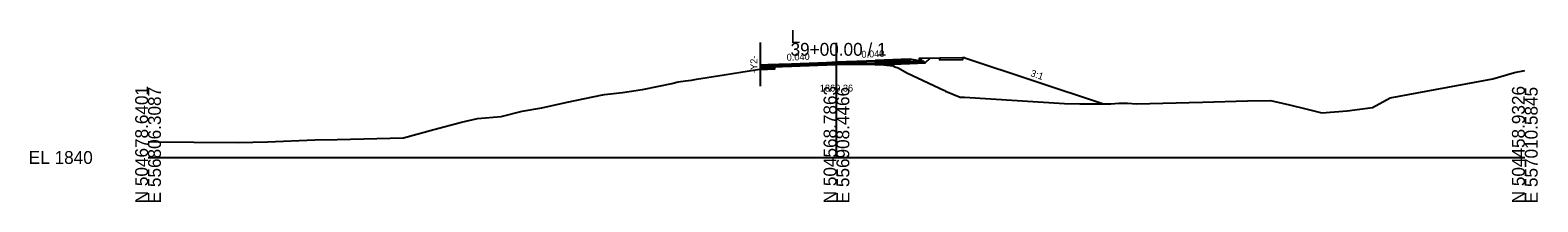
# Model space of a CAD drawing. Extents: x -26 to 4603, y -10 to 4703.
# Drawn here: x 974.3 to 1302.8, y 4395.3 to 4432.8 of the extents above; entities that cross this region are included whole.
import ezdxf

# ---------------------------------------------------------------- set-up
doc = ezdxf.new("R2010")
doc.units = 0
for name, color, linetype in [('Default', 7, 'Continuous'), ('Exist Cross Section Cell', 7, 'Continuous'), ('Exist XS Ground Line', 7, 'Continuous'), ('Prop CMT Pvmt Course 1', 7, 'Continuous'), ('Prop CMT Pvmt Course 2', 7, 'Continuous'), ('Prop CMT Pvmt Course 3', 7, 'Continuous'), ('Prop CMT Pvmt Milling', 7, 'Continuous'), ('Prop CMT Shear Line', 7, 'Continuous'), ('Prop CMT Shld Paved Course 2', 7, 'Continuous'), ('Prop CMT Subgrade Earthwork', 7, 'Continuous'), ('Prop Conc 4in Sidewalk', 7, 'Continuous'), ('Prop Conc Curb and Gutter', 7, 'Continuous'), ('Prop Corridor Mesh Bottom', 7, 'Continuous'), ('Prop XS Finish Grade', 7, 'Continuous'), ('Prop XS Label Text', 7, 'Continuous'), ('Prop XS Shear Point Element', 7, 'Continuous'), ('Prop XS Shear Point Label', 7, 'Continuous'), ('Prop XS SS Elevation Text', 7, 'Continuous')]:
    doc.layers.add(name, color=color, linetype=linetype)

msp = doc.modelspace()

# ---------------------------------------------------------------- linework, layer by layer
at = {"layer": 'Exist Cross Section Cell'}
for p, q in [((1150, 4405), (1150, 4430)), ((1000, 4405), (1150, 4405)), ((1150, 4405), (1300, 4405))]:
    msp.add_line(p, q, dxfattribs=at)
at = {"layer": 'Exist XS Ground Line'}
msp.add_lwpolyline([(1000, 4408.46), (1002.27, 4408.4), (1009.98, 4408.34), (1019.64, 4408.25), (1026.01, 4408.45), (1036.39, 4408.84), (1041.2, 4408.91), (1055.66, 4409.27), (1062.27, 4411.12), (1068.29, 4412.73), (1071.75, 4413.5), (1076.96, 4413.98), (1081.53, 4415.08), (1085.8, 4415.85), (1091.34, 4417.05), (1099.05, 4418.67), (1099.12, 4418.68), (1099.43, 4418.72), (1103.35, 4419.21), (1106.31, 4419.61), (1107.18, 4419.73), (1107.77, 4419.84), (1111.33, 4420.57), (1114.11, 4421.18), (1115.53, 4421.53), (1117.09, 4421.73), (1118.41, 4421.91), (1119.52, 4422.09), (1125.54, 4423.04), (1130.98, 4423.92), (1136.01, 4424.74), (1136.36, 4424.8), (1136.6, 4424.82), (1137.42, 4424.9), (1138.22, 4424.94), (1147.88, 4425.35), (1156.59, 4425.39), (1158.5, 4425.39), (1159.18, 4425.32), (1160.32, 4425.21), (1162.39, 4424.97), (1162.75, 4424.75), (1163.43, 4424.54), (1165.36, 4423.47), (1173.52, 4419.63), (1173.75, 4419.45), (1176.93, 4418.2), (1177.14, 4418.14), (1177.89, 4418.13), (1199.71, 4416.79), (1203.04, 4416.68), (1209.81, 4416.7), (1211.56, 4416.88), (1213.4, 4416.86), (1215.35, 4416.7), (1229.8, 4417.08), (1239.59, 4417.38), (1244.6, 4417.46), (1248.75, 4416.5), (1252.55, 4415.54), (1255.77, 4414.73), (1261.32, 4415.19), (1266.84, 4415.94), (1270.64, 4418), (1293.02, 4422.14), (1297.76, 4423.56), (1300, 4423.98)], dxfattribs=at)
at = {"layer": 'Prop CMT Pvmt Course 1'}
for points in [[(1150, 4425.84), (1150, 4425.84), (1150, 4425.36), (1150, 4425.36), (1150, 4425.36), (1147.88, 4425.35), (1147.88, 4425.35), (1138.22, 4424.94), (1138.22, 4424.94), (1137.42, 4424.9), (1136.6, 4424.82), (1136.6, 4424.82), (1136.6, 4424.82), (1136.6, 4425.3), (1136.6, 4425.3), (1137.42, 4425.33), (1138.22, 4425.37), (1138.22, 4425.37), (1147.88, 4425.75), (1147.88, 4425.75), (1150, 4425.84)], [(1158.5, 4426.18), (1158.5, 4425.39), (1158.5, 4425.39), (1156.59, 4425.39), (1156.59, 4425.39), (1150, 4425.36), (1150, 4425.36), (1150, 4425.36), (1150, 4425.84), (1150, 4425.84), (1156.59, 4426.1), (1156.59, 4426.1), (1158.5, 4426.18)], [(1166, 4426.48), (1158.5, 4426.18), (1158.5, 4425.93), (1158.5, 4425.93), (1166, 4426.23), (1166, 4426.23), (1166, 4426.23), (1166, 4426.48), (1166, 4426.48)], [(1136.6, 4425.3), (1133.43, 4425.17), (1133.43, 4424.92), (1133.43, 4424.92), (1136.6, 4425.05), (1136.6, 4425.05), (1136.6, 4425.05), (1136.6, 4425.3), (1136.6, 4425.3)]]:
    msp.add_lwpolyline(points, dxfattribs=at)
at = {"layer": 'Prop CMT Pvmt Course 2'}
for points in [[(1166, 4426.23), (1158.5, 4425.93), (1158.5, 4425.59), (1158.5, 4425.59), (1166, 4425.89), (1166, 4425.89), (1166, 4425.89), (1166, 4426.23), (1166, 4426.23)], [(1136.6, 4425.05), (1133.43, 4424.92), (1133.43, 4424.59), (1133.43, 4424.59), (1136.6, 4424.72), (1136.6, 4424.72), (1136.6, 4424.72), (1136.6, 4425.05), (1136.6, 4425.05)]]:
    msp.add_lwpolyline(points, dxfattribs=at)
at = {"layer": 'Prop CMT Pvmt Course 3'}
for points in [[(1166, 4425.89), (1158.5, 4425.59), (1158.5, 4425.22), (1158.5, 4425.22), (1166, 4425.52), (1166, 4425.52), (1166, 4425.52), (1166, 4425.89), (1166, 4425.89)], [(1166, 4425.89), (1166, 4425.89), (1166, 4425.52), (1166, 4425.52), (1166, 4425.52), (1169.36, 4425.65), (1169.36, 4425.65), (1169, 4426.01), (1166, 4425.89)], [(1136.6, 4424.72), (1133.43, 4424.59), (1133.43, 4424.22), (1133.43, 4424.22), (1136.6, 4424.34), (1136.6, 4424.34), (1136.6, 4424.34), (1136.6, 4424.72), (1136.6, 4424.72)]]:
    msp.add_lwpolyline(points, dxfattribs=at)
at = {"layer": 'Prop CMT Pvmt Milling'}
for points in [[(1136.6, 4424.82), (1136.6, 4424.82), (1137.42, 4424.9), (1138.22, 4424.94), (1138.22, 4424.94), (1147.88, 4425.35), (1147.88, 4425.35), (1150, 4425.36), (1150, 4425.36)], [(1158.5, 4425.39), (1156.59, 4425.39), (1156.59, 4425.39), (1150, 4425.36), (1150, 4425.36)]]:
    msp.add_lwpolyline(points, dxfattribs=at)
at = {"layer": 'Prop CMT Shld Paved Course 2'}
for points in [[(1150, 4425.59), (1150, 4425.59), (1150, 4425.25), (1150, 4425.25), (1150, 4425.25), (1147.88, 4425.17), (1147.88, 4425.17), (1138.22, 4424.78), (1138.22, 4424.78), (1137.42, 4424.75), (1136.6, 4424.72), (1136.6, 4424.72), (1136.6, 4424.72), (1136.6, 4425.05), (1136.6, 4425.05), (1137.42, 4425.08), (1138.22, 4425.12), (1138.22, 4425.12), (1147.88, 4425.5), (1147.88, 4425.5), (1150, 4425.59)], [(1158.5, 4425.93), (1158.5, 4425.39), (1158.5, 4425.39), (1156.59, 4425.39), (1156.59, 4425.39), (1152.96, 4425.37), (1152.96, 4425.37), (1150, 4425.25), (1150, 4425.25), (1150, 4425.25), (1150, 4425.59), (1150, 4425.59), (1156.59, 4425.85), (1156.59, 4425.85), (1158.5, 4425.93)]]:
    msp.add_lwpolyline(points, dxfattribs=at)
at = {"layer": 'Prop CMT Subgrade Earthwork'}
for points in [[(1169.36, 4425.65), (1169.36, 4425.65), (1158.5, 4425.22)], [(1170.32, 4426.61), (1169.36, 4425.65), (1169.36, 4425.65)], [(1133.43, 4424.22), (1136.6, 4424.34), (1136.6, 4424.34)]]:
    msp.add_lwpolyline(points, dxfattribs=at)
at = {"layer": 'Prop Conc 4in Sidewalk'}
msp.add_lwpolyline([(1172.5, 4426.66), (1172.5, 4426.66), (1172.49, 4426.32), (1172.49, 4426.32), (1172.49, 4426.32), (1177.51, 4426.42), (1177.51, 4426.42), (1177.5, 4426.76), (1172.5, 4426.66)], dxfattribs=at)
at = {"layer": 'Prop Conc Curb and Gutter'}
msp.add_lwpolyline([(1168, 4426.08), (1166, 4426.48), (1166, 4425.89), (1166, 4425.89), (1166, 4425.89), (1168.5, 4425.99), (1168.5, 4425.99), (1168.5, 4426.58), (1168.5, 4426.58), (1168, 4426.58), (1168, 4426.08), (1168, 4426.08), (1168, 4426.08)], dxfattribs=at)
at = {"layer": 'Prop Corridor Mesh Bottom'}
msp.add_lwpolyline([(1166, 4426.48), (1166, 4426.23)], dxfattribs=at)
at = {"layer": 'Prop XS Finish Grade'}
for points in [[(1172.5, 4426.66), (1168.5, 4426.58), (1168.5, 4426.58)], [(1178, 4426.77), (1177.5, 4426.76), (1177.5, 4426.76)], [(1178, 4426.77), (1208.23, 4416.69)]]:
    msp.add_lwpolyline(points, dxfattribs=at)
at = {"layer": 'Prop XS Shear Point Element'}
msp.add_line((1133.43, 4420.58), (1133.43, 4430.07), dxfattribs=at)

# ---------------------------------------------------------------- texts
at = {"layer": 'Default'}
msp.add_text('-', height=0.0001, dxfattribs=at).set_placement((1000, 4405))
at = {"layer": 'Exist Cross Section Cell'}
for s, p in [('L', (1140, 4430)), ('39+00.00 / 1', (1140, 4427.2)), ('EL 1840', (974, 4403.6))]:
    msp.add_text(s, height=2.8, dxfattribs=at).set_placement(p)
for s, p in [('N 504678.6401', (1000, 4395)), ('E 556806.3087', (1002.8, 4395)), ('N 504568.7863', (1150, 4395)), ('E 556908.4466', (1152.8, 4395)), ('N 504458.9326', (1300, 4395)), ('E 557010.5845', (1302.8, 4395))]:
    msp.add_text(s, height=2.8, rotation=90, dxfattribs=at).set_placement(p)
at = {"layer": 'Prop CMT Shear Line'}
for p in [(1150, 4425.84), (1166, 4426.48), (1166, 4426.48), (1168, 4426.08), (1172.5, 4426.66), (1177.5, 4426.76), (1178, 4426.77), (1133.43, 4425.17), (1208.23, 4416.69)]:
    msp.add_text('X', height=0.0025, dxfattribs=at).set_placement(p)
at = {"layer": 'Prop XS Label Text'}
for s, rotation, p in [('0.040', 2.2906, (1139.18, 4426.11)), ('0.040', 2.2906, (1155.47, 4426.76)), ('3:1', 341.5668, (1192.17, 4422.78))]:
    msp.add_text(s, height=1.5, rotation=rotation, dxfattribs=at).set_placement(p)
at = {"layer": 'Prop XS Shear Point Label'}
msp.add_text('-Y2-', height=1.5, rotation=90, dxfattribs=at).set_placement((1132.75, 4423.44))
at = {"layer": 'Prop XS SS Elevation Text'}
msp.add_text('1860.36', height=1.5, dxfattribs=at).set_placement((1146.38, 4419.39))

doc.saveas('drawing.dxf')
